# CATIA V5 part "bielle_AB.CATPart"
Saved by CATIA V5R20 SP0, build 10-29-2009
Part number: bielle_AB
Bounding box of the stored display mesh (mm): x -4 to 7, y -33.618 to 3.996, z -3.999 to 8.743
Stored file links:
  D:\Dropbox\IAO_2012\IAO_2012_753_jrecappe\jrecappe.zip\bielle_AB.CATPart
  D:\Dropbox\IAO_2012\IAO_2012_753_jrecappe\jrecappe.zip\Ass_brevetIAO_skl.CATProduct
  D:\Dropbox\IAO_2012\IAO_2012_753_jrecappe\jrecappe.zip\Ass_skl_levier2bras.CATProduct
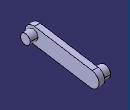
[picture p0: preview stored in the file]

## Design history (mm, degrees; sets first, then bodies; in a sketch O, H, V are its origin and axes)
Set1
  Point1 "Point A": linked copy from another document
  Point2 "PoinT B": linked copy from another document
Body1 (main body)
  Sketch1 on yz-plane, origin (0, 0, 0), H (0, 1, 0), V (0, 0, 1)
    construction line L1 (0, 0) -> (-29.6225, 4.744)
    point P1 (0, 0)
    point P2 (-29.6225, 4.744)
    line L2 (-0.6325, -3.9497) -> (-30.2551, 0.7943)
    line L3 (-28.99, 8.6936) -> (0.6325, 3.9497)
    arc A1 centre (-29.6225, 4.744) radius 4 from (-30.2551, 0.7943) to (-28.99, 8.6936) cw
    arc A2 centre (0, 0) radius 4 from (0.6325, 3.9497) to (-0.6325, -3.9497) cw
    reference projected point E1 (0, 0) from Point1
    reference projected point E2 (-29.6225, 4.744) from Point2
    distance L1 L2 = 4
    tangency: A1 L2, A2 L2, A1 L3, A2 L3
    coincidence: P1 E1, P2 E2
  Pad1: profile Sketch1, direction (1, 0, 0), length 3
  Sketch2 on yz-plane, origin (0, 0, 0), H (0, 1, 0), V (0, 0, 1)
    circle A1 centre (0, 0) radius 3
    point P1 (0, 0)
    reference projected point E1 (0, 0) from Point1
    coincidence: P1 V, P1 E1
  Pad2: profile Sketch2, direction (1, 0, 0), length -4
  Sketch3 on yz-plane, origin (0, 0, 0), H (0, 1, 0), V (0, 0, 1)
    circle A1 centre (-29.6225, 4.744) radius 2.5
    point P1 (-29.6225, 4.744)
    reference projected point E1 (-29.6225, 4.744) from Point2
    coincidence: P1 E1
  Pad3: profile Sketch3, direction (1, 0, 0), length 7, opposite side length -3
